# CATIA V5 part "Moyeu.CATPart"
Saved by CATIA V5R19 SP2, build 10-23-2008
Part number: Moyeu
Bounding box of the stored display mesh (mm): x -119.843 to 119.843, y -945 to -765, z -119.843 to 119.843
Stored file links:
  G:\EU_thinkMotion\CFAO_2010\MMS_groupe3\MMS_groupe3\pmayet\pmayet_assemblage_animation\pmayet_assemblage_animation\Moyeu.CATPart
  G:\EU_thinkMotion\CFAO_2010\MMS_groupe3\MMS_groupe3\pmayet\pmayet_assemblage_animation\pmayet_assemblage_animation\pmayet_assemblage_animation.CATProduct
  G:\EU_thinkMotion\CFAO_2010\MMS_groupe3\MMS_groupe3\pmayet\pmayet_assemblage_animation\pmayet_assemblage_animation\Squelette_porte_moyeu.CATPart
  G:\EU_thinkMotion\CFAO_2010\MMS_groupe3\MMS_groupe3\pmayet\pmayet_assemblage_animation\pmayet_assemblage_animation\Porte_moyeu.CATPart
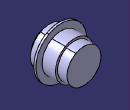
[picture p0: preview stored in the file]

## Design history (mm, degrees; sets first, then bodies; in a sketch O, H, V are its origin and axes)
Parameters
  Rayon_porte_moyeu = 80 mm
  `Epaisseur_port-moyeu` = 10 mm
  Longueur_moyeu = 180 mm
Set1
  DatumCurve1: linked copy from another document
Set2
  Plane1: linked copy from another document
  Point1: linked copy from another document
  DatumCurve2: linked copy from another document
  Plane2: linked copy from another document
Body1 (main body)
  Sketch1 on Plane1, origin (0, 0, 0), H (0, 1, 0), V (0, 0, 1)
    line L1 (-810, 80) -> (-765, 80)
    point P1 (-810, 80)
    point P2 (-765, 80)
    reference projected point E1 (-800, 0) from Point1
    reference projected line E2 (-810, 130) -> (-810, -130) from edge of DatumCurve2
    line L2 (-765, 80) -> (-765, 0)
    point P3 (-765, 80)
    point P4 (-765, 0)
    reference intersected line E3 through (0, 0) direction (-1, 0) from Plane2
    line L3 (-810, 90) -> (-810, 80)
    point P5 (-810, 90)
    point P6 (-810, 80)
    reference projected line E4 (-810, 130) -> (-810, -130) from edge of DatumCurve2
    line L4 (-873, 90) -> (-810, 90)
    point P7 (-873, 90)
    point P8 (-810, 90)
    reference projected point E5 (-800, 0) from Point1
    line L5 (-873, 90) -> (-873, 120)
    point P9 (-873, 90)
    point P10 (-873, 120)
    line L6 (-873, 120) -> (-883, 120)
    point P11 (-873, 120)
    point P12 (-883, 120)
    line L7 (-883, 120) -> (-883, 90)
    point P13 (-883, 120)
    point P14 (-883, 90)
    line L8 (-883, 90) -> (-928, 90)
    point P15 (-883, 90)
    point P16 (-928, 90)
    line L9 (-945, 70) -> (-945, 0)
    point P17 (-945, 70)
    point P18 (-945, 0)
    reference intersected line E6 through (0, 0) direction (-1, 0) from Plane2
    line L10 (-928, 90) -> (-945, 70)
    point P19 (-928, 90)
    point P20 (-945, 70)
    line L11 (-945, 0) -> (-765, 0)
    point P21 (-945, 0)
    point P22 (-765, 0)
    axis line L12 (-640, 0) -> (-610, 0)
    point P23 (-640, 0)
    distance E1 L1 = 80 {= Rayon_porte_moyeu}
    distance E2 P1 = 0
    length L1 = 45 {= Longueur_moyeu *0.25}
    distance E3 P4 = 0
    length L3 = 10 {= `Epaisseur_port-moyeu`}
    distance L4 E5 = 90 {= Rayon_porte_moyeu +`Epaisseur_port-moyeu`}
    distance P5 P8 = 0
    length L4 = 63 {= Longueur_moyeu *0.35}
    length L5 = 30 {= `Epaisseur_port-moyeu` *3}
    length L6 = 10 {= Longueur_moyeu / 18}
    length L7 = 30 {= `Epaisseur_port-moyeu` *3}
    distance L2 L9 = 180 {= Longueur_moyeu}
    distance P18 E6 = 0
    length L9 = 70 {= Rayon_porte_moyeu -10mm}
    length L8 = 45 {= Longueur_moyeu/4}
    distance P22 P4 = 0
    horizontal: L1 H, L4 H, L6 H, L8 H, L11 H, L12 H
    vertical: L2 V, L3 V, L5 V, L7 V, L9 V
    coincidence: P2 L2, P3 P2, E4 L3, P6 L1, L5 P7, P9 L4, L6 P10, P11 L5, L7 P12, P13 P12, P15 P14, P19 P16, P20 P17, P21 P18, P23 L11, P7 P9, P10 P11
  Shaft1: profile Sketch1, axis Sketch1.L12, angle 360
